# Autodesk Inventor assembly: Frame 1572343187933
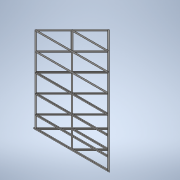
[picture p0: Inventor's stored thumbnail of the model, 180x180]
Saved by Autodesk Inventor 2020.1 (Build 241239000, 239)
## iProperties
_FrameDoc: Frame Assembly
_Version: 15.0.0
Created: 2019-10
Part Number: Frame 1572343187933
Document SubType Name: Assembly
Designer: Synergysoft Dell02
Author: Synergysoft Dell02
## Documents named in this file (31)
- C:\Users\Synergysoft Dell02\Desktop\INV-01 Intro to Modeling_2020\FRAME\Frame\Frame\Frame 1572343187933.iam
- C:\Users\Synergysoft Dell02\Desktop\INV-01 Intro to Modeling_2020\FRAME\Frame\Frame\Skeleton 1572343187934.ipt
- C:\Users\Synergysoft Dell02\Desktop\INV-01 Intro to Modeling_2020\FRAME\Frame\Frame\ISO 100x100x4 1572343189715.ipt
- C:\Users\Synergysoft Dell02\Desktop\INV-01 Intro to Modeling_2020\FRAME\Frame\Frame\ISO 100x100x4 1572343189716.ipt
- C:\Users\Synergysoft Dell02\Desktop\INV-01 Intro to Modeling_2020\FRAME\Frame\Frame\ISO 100x100x4 1572343189717.ipt
- C:\Users\Synergysoft Dell02\Desktop\INV-01 Intro to Modeling_2020\FRAME\Frame\Frame\ISO 100x100x4 1572343189718.ipt
- C:\Users\Synergysoft Dell02\Desktop\INV-01 Intro to Modeling_2020\FRAME\Frame\Frame\ISO 100x100x4 1572343189719.ipt
- C:\Users\Synergysoft Dell02\Desktop\INV-01 Intro to Modeling_2020\FRAME\Frame\Frame\ISO 100x100x4 1572343189720.ipt
- C:\Users\Synergysoft Dell02\Desktop\INV-01 Intro to Modeling_2020\FRAME\Frame\Frame\ISO 100x100x4 1572343189721.ipt
- C:\Users\Synergysoft Dell02\Desktop\INV-01 Intro to Modeling_2020\FRAME\Frame\Frame\ISO 100x100x4 1572343189722.ipt
- C:\Users\Synergysoft Dell02\Desktop\INV-01 Intro to Modeling_2020\FRAME\Frame\Frame\ISO 100x100x4 1572343189723.ipt
- C:\Users\Synergysoft Dell02\Desktop\INV-01 Intro to Modeling_2020\FRAME\Frame\Frame\ISO 100x100x4 1572343189724.ipt
- C:\Users\Synergysoft Dell02\Desktop\INV-01 Intro to Modeling_2020\FRAME\Frame\Frame\ISO 100x100x4 1572343189725.ipt
- C:\Users\Synergysoft Dell02\Desktop\INV-01 Intro to Modeling_2020\FRAME\Frame\Frame\ISO 100x100x4 1572343189726.ipt
- C:\Users\Synergysoft Dell02\Desktop\INV-01 Intro to Modeling_2020\FRAME\Frame\Frame\ISO 100x100x4 1572343189727.ipt
- C:\Users\Synergysoft Dell02\Desktop\INV-01 Intro to Modeling_2020\FRAME\Frame\Frame\ISO 100x100x4 1572343189728.ipt
- C:\Users\Synergysoft Dell02\Desktop\INV-01 Intro to Modeling_2020\FRAME\Frame\Frame\ISO 100x100x4 1572343189729.ipt
- C:\Users\Synergysoft Dell02\Desktop\INV-01 Intro to Modeling_2020\FRAME\Frame\Frame\ISO 100x100x4 1572343189730.ipt
- C:\Users\Synergysoft Dell02\Desktop\INV-01 Intro to Modeling_2020\FRAME\Frame\Frame\ISO 100x100x4 1572343189731.ipt
- C:\Users\Synergysoft Dell02\Desktop\INV-01 Intro to Modeling_2020\FRAME\Frame\Frame\ISO 100x100x4 1572343189732.ipt
- C:\Users\Synergysoft Dell02\Desktop\INV-01 Intro to Modeling_2020\FRAME\Frame\Frame\ISO 100x100x4 1572343189733.ipt
- C:\Users\Synergysoft Dell02\Desktop\INV-01 Intro to Modeling_2020\FRAME\Frame\Frame\ISO 100x100x4 1572343189734.ipt
- C:\Users\Synergysoft Dell02\Desktop\INV-01 Intro to Modeling_2020\FRAME\Frame\Frame\ISO 100x100x4 1572343189735.ipt
- C:\Users\Synergysoft Dell02\Desktop\INV-01 Intro to Modeling_2020\FRAME\Frame\Frame\ISO 100x100x4 1572343189736.ipt
- C:\Users\Synergysoft Dell02\Desktop\INV-01 Intro to Modeling_2020\FRAME\Frame\Frame\ISO 100x100x4 1572343189737.ipt
- C:\Users\Synergysoft Dell02\Desktop\INV-01 Intro to Modeling_2020\FRAME\Frame\Frame\ISO 100x100x4 1572343189738.ipt
- C:\Users\Synergysoft Dell02\Desktop\INV-01 Intro to Modeling_2020\FRAME\Frame\Frame\ISO 100x100x4 1572343189739.ipt
- C:\Users\Synergysoft Dell02\Desktop\INV-01 Intro to Modeling_2020\FRAME\Frame\Frame\ISO 100x100x4 1572343189740.ipt
- C:\Users\Synergysoft Dell02\Desktop\INV-01 Intro to Modeling_2020\FRAME\Frame\Frame\ISO 100x100x4 1572343189741.ipt
- C:\Users\Synergysoft Dell02\Desktop\INV-01 Intro to Modeling_2020\FRAME\Frame\Frame\ISO 100x100x4 1572343189742.ipt
- C:\Users\Synergysoft Dell02\Desktop\INV-01 Intro to Modeling_2020\FRAME\Frame\Frame\ISO 100x100x4 1572343189743.ipt
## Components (30 placed, 2 different names)
1. Frame Reference Model
2. ISO 100x100x4:1
3. ISO 100x100x4:2
4. ISO 100x100x4:3
5. ISO 100x100x4:4
6. ISO 100x100x4:5
7. ISO 100x100x4:6
8. ISO 100x100x4:7
9. ISO 100x100x4:8
10. ISO 100x100x4:9
11. ISO 100x100x4:10
12. ISO 100x100x4:11
13. ISO 100x100x4:12
14. ISO 100x100x4:13
15. ISO 100x100x4:14
16. ISO 100x100x4:15
17. ISO 100x100x4:16
18. ISO 100x100x4:17
19. ISO 100x100x4:18
20. ISO 100x100x4:19
21. ISO 100x100x4:20
22. ISO 100x100x4:21
23. ISO 100x100x4:22
24. ISO 100x100x4:23
25. ISO 100x100x4:24
26. ISO 100x100x4:25
27. ISO 100x100x4:26
28. ISO 100x100x4:27
29. ISO 100x100x4:28
30. ISO 100x100x4:29
